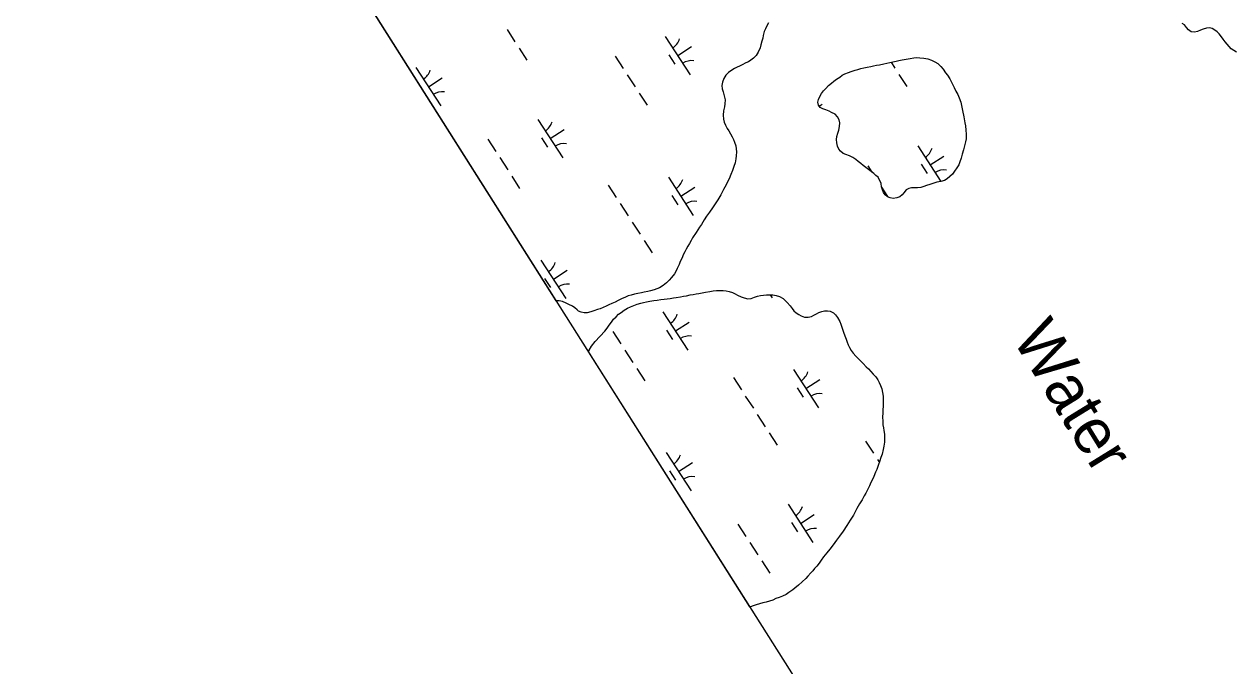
# Model space of a CAD drawing. Extents: x 3953924 to 3974542, y 193747 to 216192.
# Drawn here: x 3961029 to 3962352, y 203288 to 203989 of the extents above; entities that cross this region are included whole.
import ezdxf

# ---------------------------------------------------------------- set-up
doc = ezdxf.new("R2010")
doc.units = 0
for name, color, linetype in [('V-GRID-FRAM', 7, 'Continuous'), ('V-RIVR-IDEN', 7, 'Continuous'), ('V-WETL-SWMP', 7, 'Continuous')]:
    doc.layers.add(name, color=color, linetype=linetype)

msp = doc.modelspace()

# ---------------------------------------------------------------- linework, layer by layer
at = {"layer": 'V-GRID-FRAM'}
msp.add_lwpolyline([(3964669.3, 213787.9), (3972946, 201072.9), (3966057, 196668.5), (3957950.8, 209463.9), (3964669.3, 213787.9)], dxfattribs=at)
at = {"layer": 'V-WETL-SWMP'}
for p, q in [((3961610.9, 203686.6), (3961079.1, 204526)), ((3961557, 203983), (3961565.7, 203969.5)), ((3961839.8, 203984), (3961838.5, 203981)), ((3961841.2, 203987), (3961839.8, 203984)), ((3961843.1, 203990.3), (3961841.2, 203987)), ((3962298.3, 203988.1), (3962295.6, 203989.8)), ((3962300.6, 203985.2), (3962298.3, 203988.1)), ((3962302.8, 203982.9), (3962300.6, 203985.2)), ((3962305.5, 203980.6), (3962302.8, 203982.9)), ((3962315.8, 203982.4), (3962312.3, 203981)), ((3962318.8, 203983.5), (3962315.8, 203982.4)), ((3962322.5, 203984.5), (3962318.8, 203983.5)), ((3962325.5, 203984.8), (3962322.5, 203984.5)), ((3962328.6, 203984.1), (3962325.5, 203984.8)), ((3962331.6, 203982.4), (3962328.6, 203984.1)), ((3962334, 203980.5), (3962331.6, 203982.4)), ((3961730.1, 203975.5), (3961757.3, 203933.6)), ((3961835.9, 203970.3), (3961834.8, 203966.3)), ((3961836.7, 203973.5), (3961835.9, 203970.3)), ((3961837.3, 203976.6), (3961836.7, 203973.5)), ((3961838.5, 203981), (3961837.3, 203976.6)), ((3962309.3, 203980.1), (3962305.5, 203980.6)), ((3962312.3, 203981), (3962309.3, 203980.1)), ((3962336.1, 203978.2), (3962334, 203980.5)), ((3962338.6, 203975.1), (3962336.1, 203978.2)), ((3962340.6, 203972.4), (3962338.6, 203975.1)), ((3962342.9, 203969.5), (3962340.6, 203972.4)), ((3962344.8, 203967), (3962342.9, 203969.5)), ((3961570.1, 203962.8), (3961578.8, 203949.4)), ((3961734, 203955.4), (3961740.5, 203945.3)), ((3961743.7, 203954.5), (3961758.8, 203964.4)), ((3961831.8, 203958.3), (3961829.6, 203954.7)), ((3961833.8, 203963.1), (3961831.8, 203958.3)), ((3961834.8, 203966.3), (3961833.8, 203963.1)), ((3962347, 203964.6), (3962344.8, 203967)), ((3962349.4, 203962.1), (3962347, 203964.6)), ((3962352.1, 203960), (3962349.4, 203962.1)), ((3962355.1, 203958.3), (3962352.1, 203960)), ((3961675.3, 203953.8), (3961684, 203940.4)), ((3961808.8, 203941.8), (3961806, 203940.5)), ((3961811.5, 203943.1), (3961808.8, 203941.8)), ((3961814.2, 203944.5), (3961811.5, 203943.1)), ((3961818.2, 203946.6), (3961814.2, 203944.5)), ((3961821.1, 203947.8), (3961818.2, 203946.6)), ((3961823.8, 203949.5), (3961821.1, 203947.8)), ((3961826.7, 203951.8), (3961823.8, 203949.5)), ((3961829.6, 203954.7), (3961826.7, 203951.8)), ((3961977.2, 203947.2), (3961981.4, 203940.7)), ((3961457.2, 203941.4), (3961484.5, 203899.5)), ((3961470.9, 203920.4), (3961486, 203930.2)), ((3961688.4, 203933.7), (3961697.1, 203920.3)), ((3961794.2, 203929.7), (3961792.7, 203925.6)), ((3961796.4, 203933.1), (3961794.2, 203929.7)), ((3961799.4, 203936.2), (3961796.4, 203933.1)), ((3961802.8, 203938.8), (3961799.4, 203936.2)), ((3961806, 203940.5), (3961802.8, 203938.8)), ((3961985.8, 203934), (3961994.5, 203920.6)), ((3961792.7, 203925.6), (3961792, 203921.7)), ((3961792, 203921.7), (3961792.2, 203918.3)), ((3961792.2, 203918.3), (3961793.4, 203914.8)), ((3961701.5, 203913.6), (3961710.2, 203900.2)), ((3961793.4, 203914.8), (3961794.7, 203910.5)), ((3961794.7, 203910.5), (3961795.5, 203906.1)), ((3961795.4, 203902), (3961794.9, 203898.7)), ((3961795.5, 203906.1), (3961795.4, 203902)), ((3961793.9, 203894), (3961793.4, 203889.3)), ((3961793.4, 203889.3), (3961793.8, 203885.1)), ((3961794.9, 203898.7), (3961793.9, 203894)), ((3961898.5, 203899.4), (3961901.7, 203901.4)), ((3961590.7, 203884.8), (3961617.9, 203842.8)), ((3961793.8, 203885.1), (3961794.7, 203881.7)), ((3961794.7, 203881.7), (3961796, 203878.6)), ((3961796, 203878.6), (3961797.9, 203875)), ((3961535.9, 203863.1), (3961544.6, 203849.7)), ((3961594.6, 203864.6), (3961601.1, 203854.6)), ((3961604.3, 203863.8), (3961619.4, 203873.6)), ((3961797.9, 203875), (3961799.7, 203872.2)), ((3961799.7, 203872.2), (3961801.5, 203869.2)), ((3961801.5, 203869.2), (3961803.4, 203865.9)), ((3961803.4, 203865.9), (3961804.7, 203862.8)), ((3961804.7, 203862.8), (3961805.9, 203859.9)), ((3961805.9, 203859.9), (3961807.2, 203856)), ((3961807.2, 203856), (3961807.8, 203852.8)), ((3961807.8, 203852.8), (3961808.1, 203849.2)), ((3961808.1, 203849.2), (3961807.8, 203845)), ((3962006.4, 203855.9), (3962031.7, 203817)), ((3961549, 203843), (3961557.7, 203829.6)), ((3961806.5, 203837.5), (3961805.2, 203833.3)), ((3961807.4, 203841.7), (3961806.5, 203837.5)), ((3961807.8, 203845), (3961807.4, 203841.7)), ((3962010.3, 203835.8), (3962016.8, 203825.7)), ((3962020, 203835), (3962035.1, 203844.8)), ((3961562.1, 203822.8), (3961570.8, 203809.4)), ((3961801.8, 203824.4), (3961799.9, 203819.9)), ((3961803.7, 203828.8), (3961801.8, 203824.4)), ((3961805.2, 203833.3), (3961803.7, 203828.8)), ((3961951.6, 203834.2), (3961956.2, 203827.2)), ((3961667.7, 203812.9), (3961676.5, 203799.5)), ((3961733.5, 203821.8), (3961760.8, 203779.9)), ((3961747.2, 203800.8), (3961762.3, 203810.7)), ((3961796.7, 203813.3), (3961794, 203808.1)), ((3961798.5, 203817.2), (3961796.7, 203813.3)), ((3961799.9, 203819.9), (3961798.5, 203817.2)), ((3961966.9, 203810.7), (3961973.4, 203800.7)), ((3961737.4, 203801.7), (3961744, 203791.6)), ((3961787.5, 203796.9), (3961784, 203791.4)), ((3961791, 203802.5), (3961787.5, 203796.9)), ((3961794, 203808.1), (3961791, 203802.5)), ((3961680.8, 203792.7), (3961689.5, 203779.3)), ((3961778.4, 203783.5), (3961775.4, 203778.9)), ((3961781.8, 203788.3), (3961778.4, 203783.5)), ((3961784, 203791.4), (3961781.8, 203788.3)), ((3961693.9, 203772.6), (3961702.6, 203759.2)), ((3961769.6, 203770.1), (3961767.5, 203766.9)), ((3961772.8, 203775), (3961769.6, 203770.1)), ((3961775.4, 203778.9), (3961772.8, 203775)), ((3961763.9, 203761), (3961760.1, 203755.3)), ((3961767.5, 203766.9), (3961763.9, 203761)), ((3961707, 203752.5), (3961715.7, 203739.1)), ((3961754.9, 203746.3), (3961753.1, 203743.1)), ((3961756.8, 203749.2), (3961754.9, 203746.3)), ((3961758.4, 203752.4), (3961756.8, 203749.2)), ((3961760.1, 203755.3), (3961758.4, 203752.4)), ((3961594.1, 203731.1), (3961621.4, 203689.1)), ((3961748.5, 203733.6), (3961746.6, 203729.5)), ((3961749.8, 203736.7), (3961748.5, 203733.6)), ((3961751.4, 203739.9), (3961749.8, 203736.7)), ((3961753.1, 203743.1), (3961751.4, 203739.9)), ((3961607.8, 203710.1), (3961622.9, 203719.9)), ((3961741.6, 203718.4), (3961740.1, 203715.9)), ((3961743.3, 203721.8), (3961741.6, 203718.4)), ((3961745.5, 203726.2), (3961743.3, 203721.8)), ((3961746.6, 203729.5), (3961745.5, 203726.2)), ((3961598, 203710.9), (3961604.6, 203700.9)), ((3961731.4, 203706), (3961727.9, 203703.2)), ((3961734.5, 203709.1), (3961731.4, 203706)), ((3961737.1, 203711.9), (3961734.5, 203709.1)), ((3961740.1, 203715.9), (3961737.1, 203711.9)), ((3961686.5, 203690.6), (3961682.3, 203688.6)), ((3961689.5, 203691.8), (3961686.5, 203690.6)), ((3961692.7, 203692.7), (3961689.5, 203691.8)), ((3961696.5, 203693.7), (3961692.7, 203692.7)), ((3961700.2, 203694.6), (3961696.5, 203693.7)), ((3961704.1, 203695.3), (3961700.2, 203694.6)), ((3961707.2, 203696), (3961704.1, 203695.3)), ((3961710.9, 203696.7), (3961707.2, 203696)), ((3961714, 203697.5), (3961710.9, 203696.7)), ((3961717.8, 203698.6), (3961714, 203697.5)), ((3961720.8, 203699.6), (3961717.8, 203698.6)), ((3961723.8, 203700.7), (3961720.8, 203699.6)), ((3961727.9, 203703.2), (3961723.8, 203700.7)), ((3961739, 203689.7), (3961742.2, 203690.2)), ((3961742.2, 203690.2), (3961746.9, 203691)), ((3961746.9, 203691), (3961750.1, 203691.6)), ((3961750.1, 203691.6), (3961753.2, 203692.1)), ((3961753.2, 203692.1), (3961757.5, 203692.9)), ((3961757.5, 203692.9), (3961760.8, 203693.4)), ((3961760.8, 203693.4), (3961764, 203694.1)), ((3961764, 203694.1), (3961767, 203694.6)), ((3961767, 203694.6), (3961770.6, 203695.4)), ((3961770.6, 203695.4), (3961774.3, 203696)), ((3961774.3, 203696), (3961778.8, 203696.8)), ((3961778.8, 203696.8), (3961782.5, 203697.3)), ((3961782.5, 203697.3), (3961786, 203697.7)), ((3961786, 203697.7), (3961790.1, 203697.8)), ((3961790.1, 203697.8), (3961793.6, 203697.8)), ((3961793.6, 203697.8), (3961796.9, 203697.4)), ((3961796.9, 203697.4), (3961800.1, 203696.7)), ((3961800.1, 203696.7), (3961803.8, 203695.5)), ((3961803.8, 203695.5), (3961806.5, 203694.2)), ((3961806.5, 203694.2), (3961809.3, 203692.6)), ((3961809.3, 203692.6), (3961813.2, 203690.8)), ((3961813.2, 203690.8), (3961816.5, 203689.7)), ((3961824.1, 203689.2), (3961827.9, 203690.5)), ((3961827.9, 203690.5), (3961831.2, 203691.6)), ((3961831.2, 203691.6), (3961834.4, 203692.4)), ((3961834.4, 203692.4), (3961837.5, 203692.8)), ((3961837.5, 203692.8), (3961840.8, 203693.2)), ((3961840.8, 203693.2), (3961844.7, 203693.2)), ((3961844.7, 203693.2), (3961848, 203693)), ((3961845, 203693.2), (3961847.1, 203689.9)), ((3961848, 203693), (3961851.6, 203692.4)), ((3961851.6, 203692.4), (3961855.2, 203691.2)), ((3961855.2, 203691.2), (3961859, 203689)), ((3961614, 203686.6), (3961610.9, 203686.6)), ((3961617.5, 203685.7), (3961614, 203686.6)), ((3961621.7, 203684.1), (3961617.5, 203685.7)), ((3961624.6, 203682.6), (3961621.7, 203684.1)), ((3961628.5, 203680.5), (3961624.6, 203682.6)), ((3961631.1, 203678.7), (3961628.5, 203680.5)), ((3961633.7, 203676.5), (3961631.1, 203678.7)), ((3961659, 203677.9), (3961656.1, 203676.9)), ((3961662.1, 203679.2), (3961659, 203677.9)), ((3961665.5, 203680.7), (3961662.1, 203679.2)), ((3961668.3, 203682), (3961665.5, 203680.7)), ((3961671.6, 203683.6), (3961668.3, 203682)), ((3961675.2, 203685.2), (3961671.6, 203683.6)), ((3961678.5, 203686.9), (3961675.2, 203685.2)), ((3961682.3, 203688.6), (3961678.5, 203686.9)), ((3961685, 203676.2), (3961688.8, 203678.6)), ((3961688.8, 203678.6), (3961692.1, 203680)), ((3961692.1, 203680), (3961695.8, 203681.5)), ((3961695.8, 203681.5), (3961699.5, 203682.7)), ((3961699.5, 203682.7), (3961703.3, 203683.8)), ((3961703.3, 203683.8), (3961706.3, 203684.5)), ((3961706.3, 203684.5), (3961709.7, 203685.3)), ((3961709.7, 203685.3), (3961713.3, 203686.1)), ((3961713.3, 203686.1), (3961717.5, 203686.8)), ((3961717.5, 203686.8), (3961721.3, 203687.2)), ((3961721.3, 203687.2), (3961725.1, 203687.8)), ((3961725.1, 203687.8), (3961729.1, 203688.3)), ((3961729.1, 203688.3), (3961732.1, 203688.7)), ((3961732.1, 203688.7), (3961735.6, 203689.2)), ((3961735.6, 203689.2), (3961739, 203689.7)), ((3961816.5, 203689.7), (3961820.3, 203688.7)), ((3961820.3, 203688.7), (3961824.1, 203689.2)), ((3961859, 203689), (3961861.4, 203687)), ((3961861.4, 203687), (3961863.6, 203684.7)), ((3961863.6, 203684.7), (3961866.8, 203681)), ((3961866.8, 203681), (3961869, 203678.1)), ((3961869, 203678.1), (3961870.8, 203675.7)), ((3961635.2, 203675.2), (3961633.7, 203676.5)), ((3961638, 203674.1), (3961635.2, 203675.2)), ((3961641.5, 203673.2), (3961638, 203674.1)), ((3961644.7, 203673.5), (3961641.5, 203673.2)), ((3961648.5, 203674.4), (3961644.7, 203673.5)), ((3961652.1, 203675.5), (3961648.5, 203674.4)), ((3961656.1, 203676.9), (3961652.1, 203675.5)), ((3961671.3, 203663.2), (3961673.5, 203666.4)), ((3961673.5, 203666.4), (3961676.3, 203669)), ((3961676.3, 203669), (3961679.1, 203671.8)), ((3961679.1, 203671.8), (3961681.7, 203673.9)), ((3961681.7, 203673.9), (3961685, 203676.2)), ((3961727.6, 203674.4), (3961754.8, 203632.5)), ((3961870.8, 203675.7), (3961873.2, 203673.5)), ((3961873.2, 203673.5), (3961876.2, 203671.4)), ((3961876.2, 203671.4), (3961879, 203670.1)), ((3961879, 203670.1), (3961882.6, 203668.6)), ((3961882.6, 203668.6), (3961886.3, 203668.5)), ((3961886.3, 203668.5), (3961890, 203669.5)), ((3961890, 203669.5), (3961892.8, 203670.8)), ((3961892.8, 203670.8), (3961895.5, 203672.3)), ((3961895.5, 203672.3), (3961898.3, 203673.6)), ((3961898.3, 203673.6), (3961901.3, 203674.8)), ((3961901.3, 203674.8), (3961904.3, 203675.5)), ((3961904.3, 203675.5), (3961907.6, 203675.6)), ((3961907.6, 203675.6), (3961910.7, 203675)), ((3961910.7, 203675), (3961914.3, 203673.4)), ((3961914.3, 203673.4), (3961916.4, 203671.1)), ((3961916.4, 203671.1), (3961918.5, 203668.3)), ((3961918.5, 203668.3), (3961921, 203663.9)), ((3961921, 203663.9), (3961922.2, 203660.9)), ((3961653.5, 203642), (3961664, 203653.4)), ((3961664, 203653.4), (3961666.4, 203656.7)), ((3961666.4, 203656.7), (3961668.7, 203660)), ((3961668.7, 203660), (3961671.3, 203663.2)), ((3961672.8, 203652.8), (3961681.5, 203639.3)), ((3961731.5, 203654.3), (3961738, 203644.2)), ((3961741.2, 203653.5), (3961756.3, 203663.3)), ((3961922.2, 203660.9), (3961923.8, 203656.6)), ((3961923.8, 203656.6), (3961925.2, 203652.3)), ((3961925.2, 203652.3), (3961926.7, 203648.1)), ((3961649.5, 203637), (3961653.5, 203642)), ((3961926.7, 203648.1), (3961928.1, 203644.5)), ((3961928.1, 203644.5), (3961929.1, 203641.4)), ((3961929.1, 203641.4), (3961930.2, 203638.3)), ((3961930.2, 203638.3), (3961931.6, 203635.3)), ((3961646.5, 203630.3), (3961647, 203632.4)), ((3961822.8, 203352.1), (3961646.5, 203630.3)), ((3961647, 203632.4), (3961649.5, 203637)), ((3961685.9, 203632.6), (3961694.6, 203619.2)), ((3961931.6, 203635.3), (3961933.5, 203632.1)), ((3961933.5, 203632.1), (3961935.8, 203629.1)), ((3961935.8, 203629.1), (3961938.5, 203626)), ((3961938.5, 203626), (3961941.5, 203623.1)), ((3961699, 203612.5), (3961707.7, 203599.1)), ((3961870.4, 203611.5), (3961897.7, 203569.6)), ((3961941.5, 203623.1), (3961944.3, 203620.3)), ((3961944.3, 203620.3), (3961946.6, 203618.1)), ((3961946.6, 203618.1), (3961950.1, 203614.5)), ((3961950.1, 203614.5), (3961952.4, 203612.1)), ((3961952.4, 203612.1), (3961954.9, 203609.4)), ((3961804.6, 203602.5), (3961813.4, 203589.1)), ((3961884.1, 203590.5), (3961899.2, 203600.3)), ((3961954.9, 203609.4), (3961957.7, 203606.3)), ((3961957.7, 203606.3), (3961960.5, 203603.3)), ((3961960.5, 203603.3), (3961962.6, 203600)), ((3961962.6, 203600), (3961964, 203597.3)), ((3961874.3, 203591.3), (3961880.9, 203581.3)), ((3961964, 203597.3), (3961965.7, 203594.1)), ((3961965.7, 203594.1), (3961967.1, 203590.4)), ((3961967.1, 203590.4), (3961967.9, 203586.4)), ((3961967.9, 203586.4), (3961968.6, 203582.2)), ((3961817.7, 203582.4), (3961826.5, 203569)), ((3961968.7, 203575), (3961968.5, 203570.8)), ((3961968.6, 203582.2), (3961968.6, 203578.3)), ((3961968.6, 203578.3), (3961968.7, 203575)), ((3961830.8, 203562.3), (3961839.5, 203548.9)), ((3961968.1, 203563.8), (3961967.9, 203559.5)), ((3961967.9, 203559.5), (3961968, 203554.4)), ((3961968.3, 203567.8), (3961968.1, 203563.8)), ((3961968.5, 203570.8), (3961968.3, 203567.8)), ((3961968, 203554.4), (3961968.3, 203551.1)), ((3961968.3, 203551.1), (3961968.9, 203547.8)), ((3961968.9, 203547.8), (3961969.4, 203544.8)), ((3961969.4, 203544.8), (3961969.9, 203540.6)), ((3961843.9, 203542.2), (3961852.6, 203528.8)), ((3961949.1, 203533.2), (3961957.8, 203519.8)), ((3961969.9, 203531.8), (3961969.4, 203527.6)), ((3961969.9, 203540.6), (3961970.1, 203536.1)), ((3961970.1, 203536.1), (3961969.9, 203531.8)), ((3961731, 203520.7), (3961758.3, 203478.8)), ((3961967.3, 203519), (3961966.1, 203515.2)), ((3961968.7, 203523.9), (3961967.3, 203519)), ((3961969.4, 203527.6), (3961968.7, 203523.9)), ((3961744.7, 203499.8), (3961759.8, 203509.6)), ((3961963.6, 203507.4), (3961961.5, 203502)), ((3961962.2, 203513.1), (3961964.4, 203509.8)), ((3961964.6, 203510.6), (3961963.6, 203507.4)), ((3961966.1, 203515.2), (3961964.6, 203510.6)), ((3961734.9, 203500.6), (3961741.5, 203490.5)), ((3961958.3, 203494.4), (3961956.5, 203490.5)), ((3961960.2, 203499.2), (3961958.3, 203494.4)), ((3961961.5, 203502), (3961960.2, 203499.2)), ((3961951.6, 203480.5), (3961949.4, 203476.2)), ((3961953.5, 203484.4), (3961951.6, 203480.5)), ((3961955, 203487.9), (3961953.5, 203484.4)), ((3961956.5, 203490.5), (3961955, 203487.9)), ((3961945.5, 203469.1), (3961942.8, 203464.5)), ((3961947.9, 203473.4), (3961945.5, 203469.1)), ((3961949.4, 203476.2), (3961947.9, 203473.4)), ((3961864.5, 203464.1), (3961891.7, 203422.2)), ((3961878.1, 203443.2), (3961893.2, 203453)), ((3961935.9, 203452.2), (3961932.5, 203446.8)), ((3961937.7, 203455.2), (3961935.9, 203452.2)), ((3961939.9, 203459.5), (3961937.7, 203455.2)), ((3961942.8, 203464.5), (3961939.9, 203459.5)), ((3961809.7, 203442.4), (3961818.4, 203429)), ((3961868.4, 203444), (3961874.9, 203433.9)), ((3961928.7, 203440.8), (3961924.7, 203434.6)), ((3961932.5, 203446.8), (3961928.7, 203440.8)), ((3961920.9, 203429.2), (3961917.5, 203424.9)), ((3961924.7, 203434.6), (3961920.9, 203429.2)), ((3961822.8, 203422.3), (3961831.5, 203408.9)), ((3961910.2, 203415), (3961907, 203411)), ((3961912.7, 203418.2), (3961910.2, 203415)), ((3961915.7, 203422.4), (3961912.7, 203418.2)), ((3961917.5, 203424.9), (3961915.7, 203422.4)), ((3961835.9, 203402.2), (3961844.6, 203388.8)), ((3961898.4, 203399.7), (3961895.8, 203396.6)), ((3961900.8, 203403), (3961898.4, 203399.7)), ((3961903.4, 203406.6), (3961900.8, 203403)), ((3961907, 203411), (3961903.4, 203406.6)), ((3961889.4, 203389.2), (3961886, 203385.5)), ((3961891.6, 203391.5), (3961889.4, 203389.2)), ((3961893.5, 203393.8), (3961891.6, 203391.5)), ((3961895.8, 203396.6), (3961893.5, 203393.8)), ((3961876, 203375.5), (3961872, 203372.4)), ((3961880, 203379.2), (3961876, 203375.5)), ((3961883.8, 203383), (3961880, 203379.2)), ((3961886, 203385.5), (3961883.8, 203383)), ((3961847.7, 203359.4), (3961844.2, 203358.2)), ((3961851.2, 203360.9), (3961847.7, 203359.4)), ((3961854.7, 203362.2), (3961851.2, 203360.9)), ((3961858.4, 203363.8), (3961854.7, 203362.2)), ((3961862.3, 203365.5), (3961858.4, 203363.8)), ((3961865.5, 203367.6), (3961862.3, 203365.5)), ((3961869.6, 203370.6), (3961865.5, 203367.6)), ((3961872, 203372.4), (3961869.6, 203370.6)), ((3961823.3, 203352.1), (3961822.8, 203352.1)), ((3961826.3, 203353), (3961823.3, 203352.1)), ((3961829.5, 203354.2), (3961826.3, 203353)), ((3961833.1, 203355.1), (3961829.5, 203354.2)), ((3961836.9, 203356.2), (3961833.1, 203355.1)), ((3961840.4, 203357.1), (3961836.9, 203356.2)), ((3961844.2, 203358.2), (3961840.4, 203357.1))]:
    msp.add_line(p, q, dxfattribs=at)
for points in [[(3961963.1, 203821.5), (3961960.6, 203823.6), (3961958.3, 203825.5), (3961955.5, 203827.7), (3961952.5, 203830), (3961949.5, 203832.2), (3961946.7, 203834.4), (3961944, 203836.6), (3961941.3, 203838.9), (3961938.6, 203841), (3961935.2, 203843.2), (3961931.6, 203845), (3961927.7, 203846.4), (3961924.9, 203847.7), (3961921.9, 203850), (3961919.9, 203852.4), (3961918.5, 203855.6), (3961917.8, 203859.1), (3961917.6, 203862.7), (3961917.9, 203866.3), (3961919, 203869.7), (3961920.1, 203873), (3961920.9, 203877), (3961921, 203880.9), (3961920.4, 203884.4), (3961918.7, 203887.7), (3961915.9, 203890.4), (3961912.1, 203892.5), (3961909.3, 203893.7), (3961905.7, 203895.1), (3961902.5, 203896.2), (3961899.6, 203897.9), (3961897.8, 203900.4), (3961897.2, 203903.5), (3961897.9, 203906.7), (3961899.1, 203909.8), (3961901.1, 203913.1), (3961903.3, 203916.1), (3961905.9, 203918.7), (3961908.8, 203921.7), (3961912.1, 203924.5), (3961914.5, 203926.5), (3961917.6, 203928.7), (3961921, 203931.1), (3961923.8, 203933.1), (3961926.7, 203934.5), (3961930.7, 203936), (3961933.6, 203937.2), (3961937.9, 203938.5), (3961940.8, 203939.3), (3961944.2, 203940.4), (3961947.4, 203941.2), (3961951, 203941.9), (3961954.9, 203942.6), (3961958, 203943.3), (3961961.4, 203944), (3961964.7, 203944.6), (3961969.1, 203945.4), (3961972.4, 203946.2), (3961976, 203946.9), (3961979.3, 203947.7), (3961982.7, 203948.5), (3961985.8, 203949.2), (3961989.3, 203949.9), (3961993.7, 203950.7), (3961998, 203951.5), (3962002.1, 203952.1), (3962005.3, 203952.3), (3962008.8, 203952.2), (3962013, 203951.8), (3962017.3, 203950.9), (3962021.6, 203949.4), (3962025, 203947.8), (3962028.2, 203945.8), (3962031.7, 203942.6), (3962034.3, 203939.8), (3962036.9, 203935.9), (3962039, 203933), (3962041.4, 203929.3), (3962044.1, 203924.1), (3962046.4, 203919.8), (3962048.2, 203915.8), (3962050.3, 203912.1), (3962051.7, 203908.5), (3962053.4, 203903.5), (3962054.4, 203899.9), (3962055.5, 203894.5), (3962056.9, 203887.5), (3962057.9, 203881), (3962058.5, 203877.8), (3962059.1, 203872.9), (3962059.5, 203868.5), (3962059.3, 203863.7), (3962058.7, 203860.4), (3962057.7, 203855.8), (3962056.5, 203851.5), (3962055.1, 203846.7), (3962054, 203842.3), (3962052.5, 203838.3), (3962051.2, 203835), (3962049.2, 203832)], [(3962049.2, 203832), (3962046.6, 203828.4), (3962044.3, 203825.1), (3962041.6, 203822.3), (3962038.7, 203819.7), (3962035.7, 203818.1), (3962031.8, 203817), (3962027.4, 203816.2), (3962023.9, 203815.1), (3962019.6, 203813.8), (3962016, 203812.6), (3962013.2, 203811.5), (3962009.6, 203810.4), (3962006, 203809.9), (3962002.9, 203809.9), (3961999.6, 203810), (3961996.6, 203809.3), (3961993.8, 203807.7), (3961991.2, 203804.6), (3961989.3, 203802.2), (3961986.7, 203800.2), (3961983.6, 203799), (3961979.6, 203798.5), (3961976.3, 203799.2), (3961973.4, 203800.2), (3961970.9, 203802.3), (3961968.8, 203805), (3961967.7, 203807.8), (3961966.9, 203811), (3961966.2, 203814.8), (3961963.1, 203821.5)]]:
    msp.add_lwpolyline(points, dxfattribs=at)
for centre, start, end in [((3961728.8, 203977.8), 302.2901, 343.8338), ((3961759, 203931.5), 82.2901, 123.8337), ((3961456, 203943.7), 302.2901, 343.8338), ((3961486.1, 203897.4), 82.2901, 123.8337), ((3961589.4, 203887.1), 302.2901, 343.8338), ((3961619.6, 203840.8), 82.2901, 123.8337), ((3962005.1, 203858.2), 302.2901, 343.8338), ((3962035.3, 203812), 82.2901, 123.8337), ((3961732.3, 203824.1), 302.2901, 343.8338), ((3961762.4, 203777.8), 82.2901, 123.8337), ((3961592.9, 203733.4), 302.2901, 343.8338), ((3961623, 203687.1), 82.2901, 123.8337), ((3961726.3, 203676.8), 302.2901, 343.8338), ((3961756.5, 203630.5), 82.2901, 123.8337), ((3961869.2, 203613.8), 302.2901, 343.8338), ((3961899.4, 203567.5), 82.2901, 123.8337), ((3961729.8, 203523.1), 302.2901, 343.8338), ((3961760, 203476.8), 82.2901, 123.8337), ((3961863.2, 203466.4), 302.2901, 343.8338), ((3961893.4, 203420.1), 82.2901, 123.8337)]:
    msp.add_arc(centre, 17.6, start, end, dxfattribs=at)

# ---------------------------------------------------------------- texts
at = {"layer": 'V-RIVR-IDEN'}
msp.add_text('Water', height=50, rotation=301.6613, dxfattribs=at).set_placement((3962108.8, 203645.7))

doc.saveas('drawing.dxf')
